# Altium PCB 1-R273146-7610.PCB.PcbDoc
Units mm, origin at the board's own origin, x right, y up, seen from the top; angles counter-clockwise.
Board outline 36.96 x 25.02 mm, 2 copper layers (Top Layer, Bottom Layer), stack 0.536 mm thick; 72 components, 82 nets, 228 pads, 80 vias.
Unrouted connection lines stored in the file: 1.
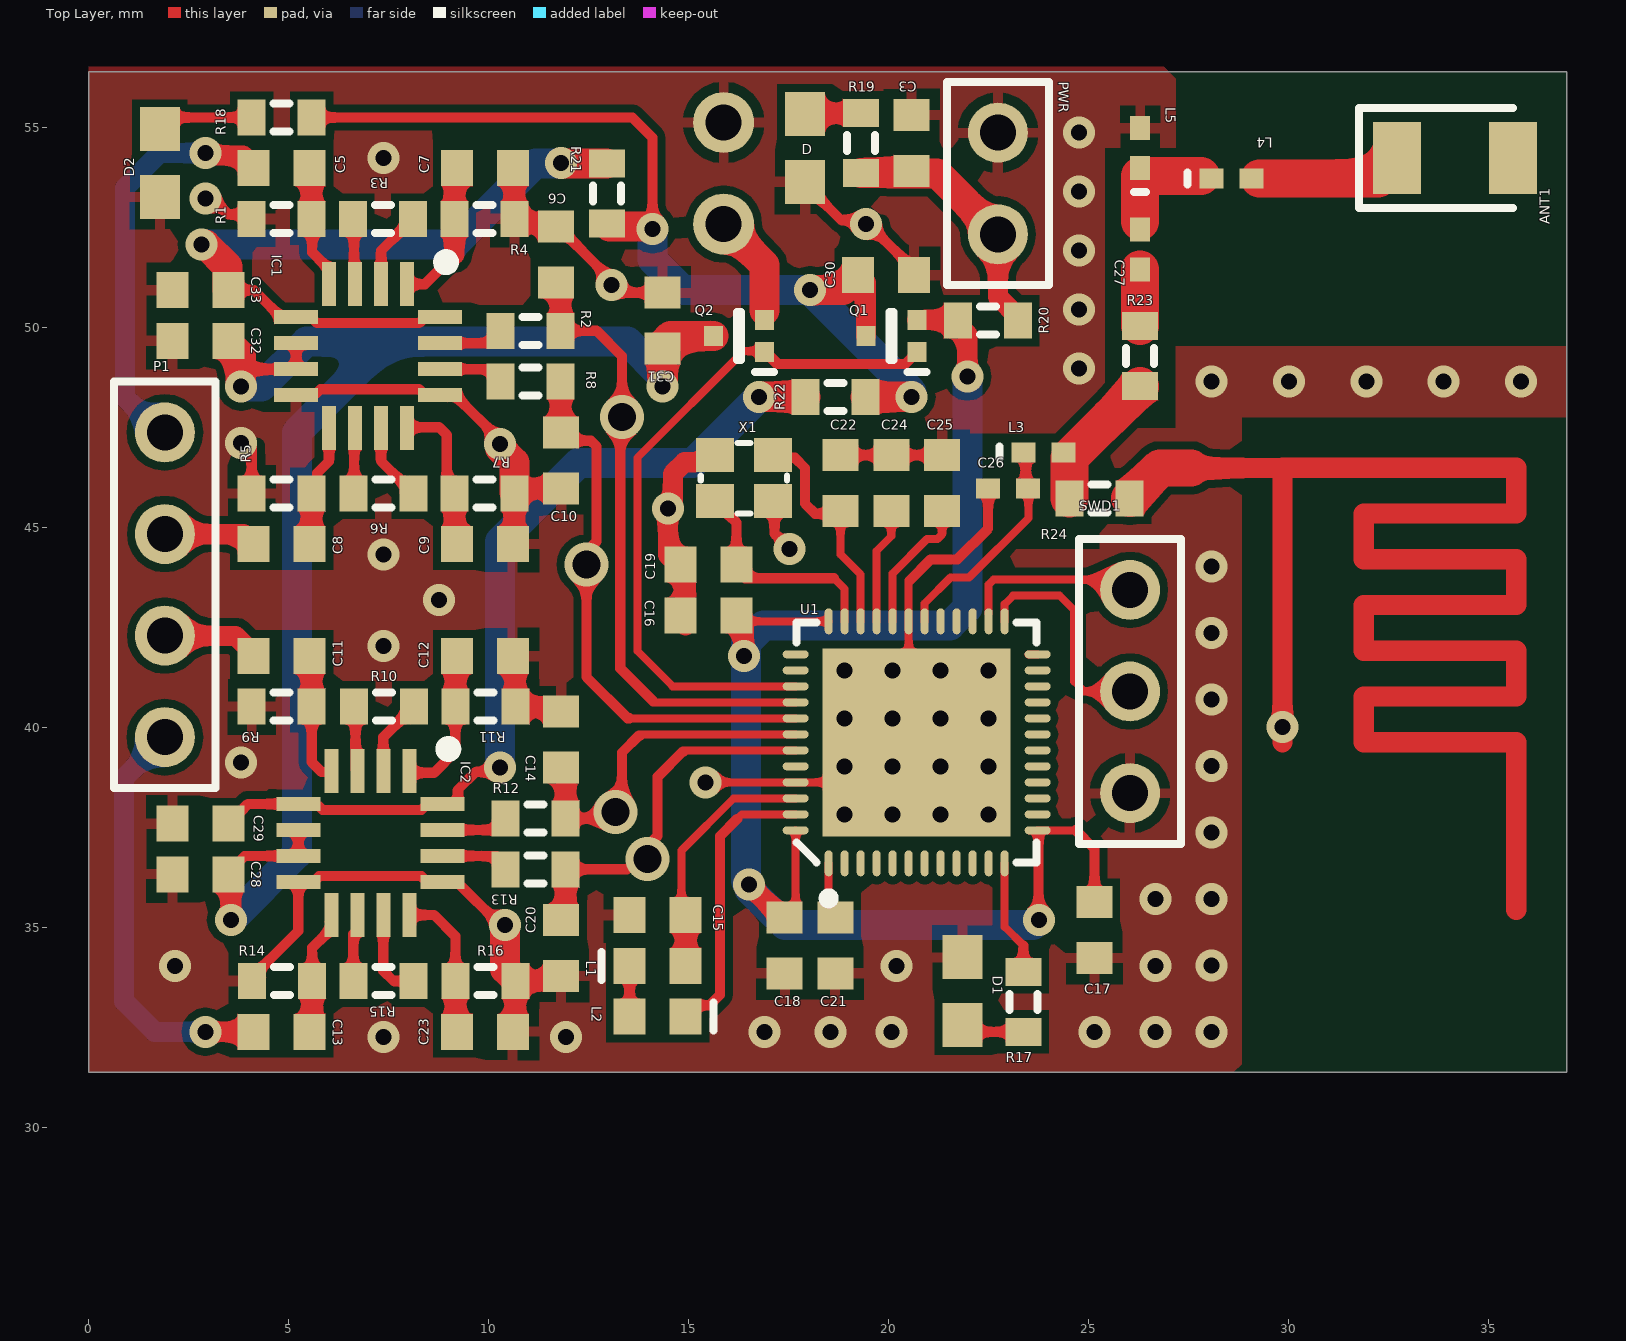
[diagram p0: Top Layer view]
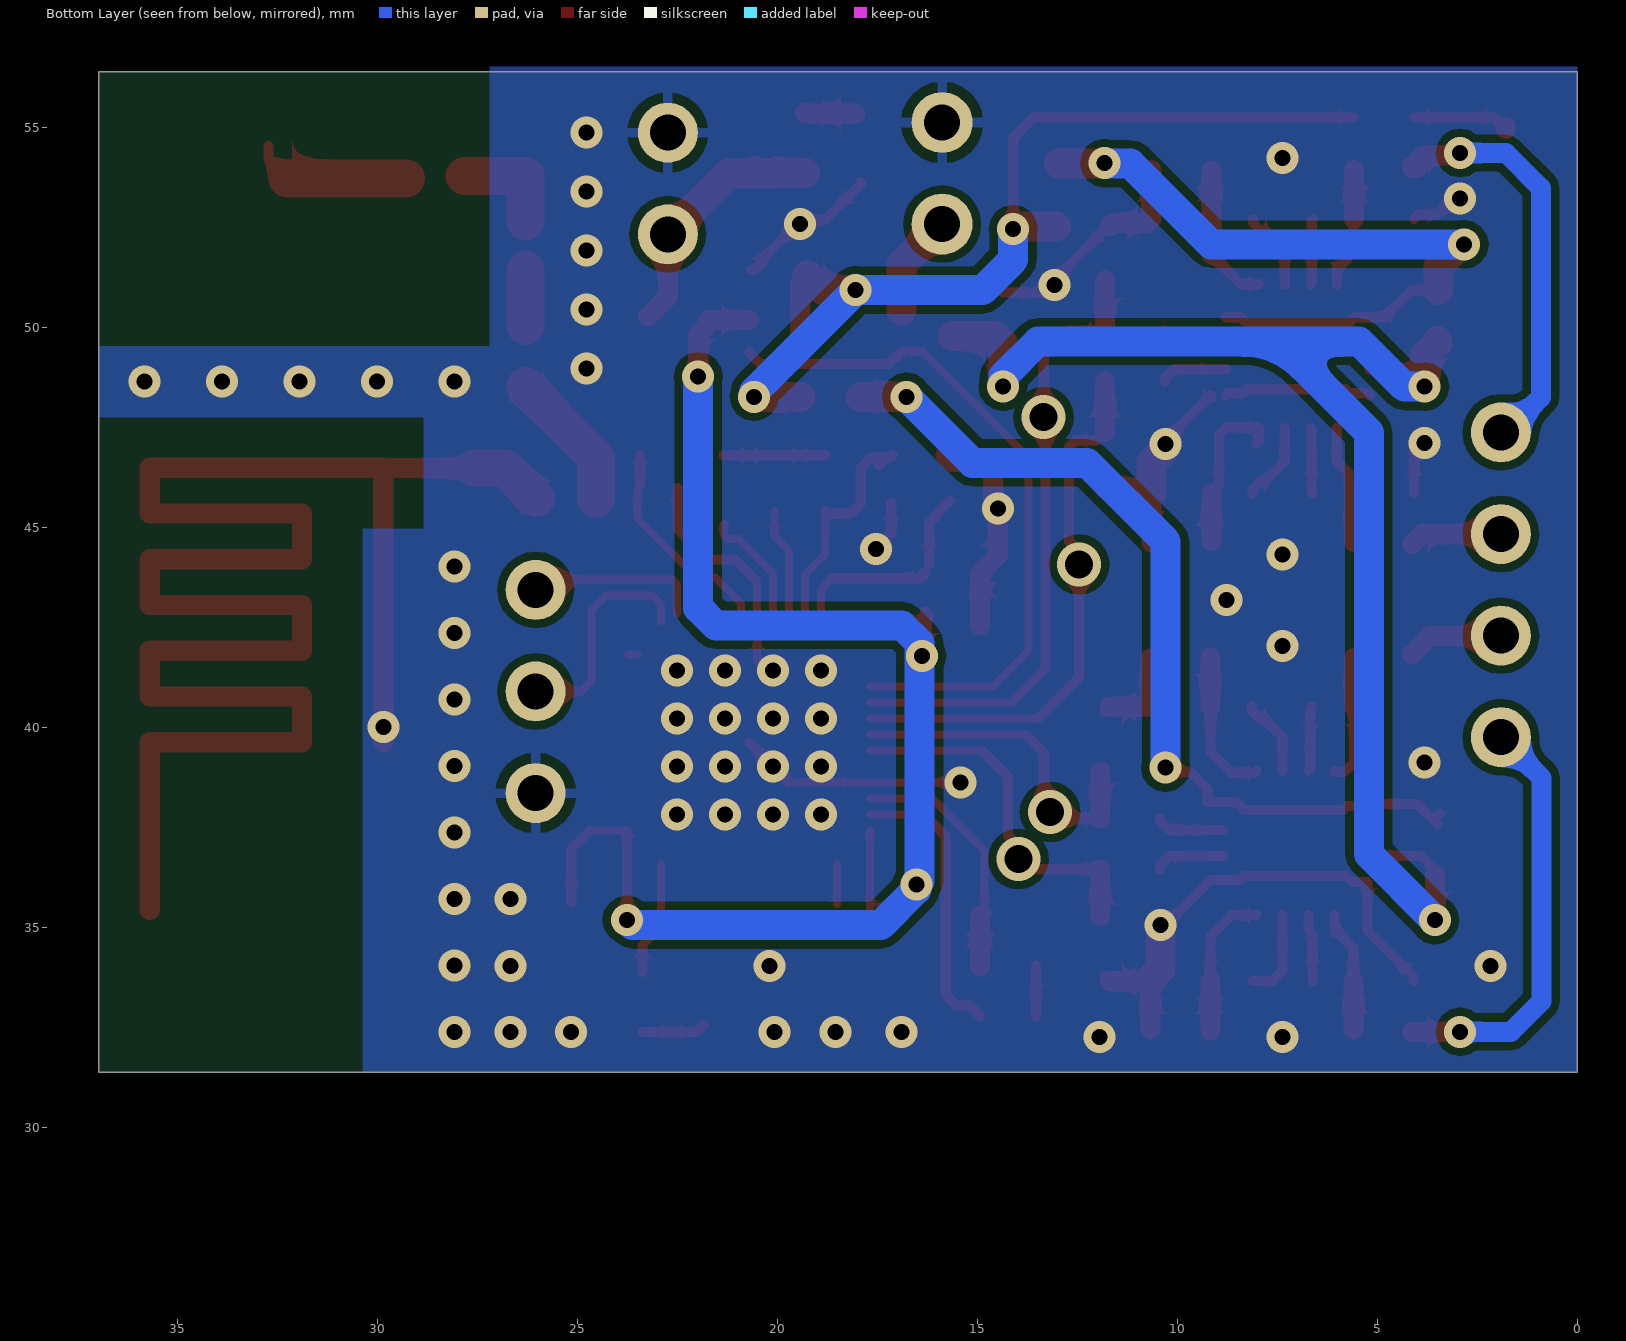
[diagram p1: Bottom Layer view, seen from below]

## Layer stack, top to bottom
Top Solder: solder mask 0.0102, Solder Resist, Dk 3.5
Top Layer: signal copper 0.018
Dielectric 1: dielectric 0.5, FR-4, Dk 4.8
Bottom Layer: signal copper 0.018
Bottom Solder: solder mask 0.0102, Solder Resist, Dk 3.5

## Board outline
0,31.369 36.957,31.369 36.957,56.388 0,56.388

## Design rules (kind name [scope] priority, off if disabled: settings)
Clearance Clearance_2 [InNamedPolygon('VSS_L01_P003')] p1: gap=0.2 ignorepadtopadclearanceinfootprint=FALSE
Clearance Clearance_1 [InNamedPolygon('VSS_L01_P003')] p2: gap=0.254 ignorepadtopadclearanceinfootprint=FALSE except(0: Arc-Hole Track-Hole SMDPad-Hole THPad-Hole Via-Hole Fill-Hole Poly-Hole Region-Hole Text-Hole)
Clearance [All] p3: gap=0.2 ignorepadtopadclearanceinfootprint=TRUE
MatchedLengths MatchLengths_xSignals_U1_L3 [InxSignalClass('xSignals_U1_L3_MatchLengthsClass')] p1: tolerance=2.54 checknetsindiffpair=FALSE checkdiffpairvsdiffpair=TRUE checkxsignals=TRUE checkothers=TRUE
PolygonConnect PolygonConnect_3 [All vs IsNamedPolygon('VSS_L02_P001')] p1: thpad.connectstyle=Relief thpad.reliefconductorwidth=0.254 thpad.reliefentries=4 thpad.polygonreliefangle="90 Angle" thpad.airgapwidth=0.254 smdpad.connectstyle=Relief smdpad.reliefconductorwidth=0.254 smdpad.reliefentries=4 smdpad.polygonreliefangle="90 Angle" smdpad.airgapwidth=0.254 via.connectstyle=Direct via.reliefconductorwidth=0.254 via.reliefentries=4 via.polygonreliefangle="90 Angle" via.airgapwidth=0.254
PolygonConnect PolygonConnect_2 [All vs IsNamedPolygon('VSS_L01_P003')] p2: thpad.connectstyle=Relief thpad.reliefconductorwidth=0.254 thpad.reliefentries=4 thpad.polygonreliefangle="90 Angle" thpad.airgapwidth=0.254 smdpad.connectstyle=Relief smdpad.reliefconductorwidth=0.254 smdpad.reliefentries=4 smdpad.polygonreliefangle="90 Angle" smdpad.airgapwidth=0.254 via.connectstyle=Direct via.reliefconductorwidth=0.254 via.reliefentries=4 via.polygonreliefangle="90 Angle" via.airgapwidth=0.254
PolygonConnect PolygonConnect_1 [All vs IsNamedPolygon('VSS_L01_P003')] p3: connectstyle=Direct reliefconductorwidth=0.254 reliefentries=4 polygonreliefangle="90 Angle" airgapwidth=0.254
PolygonConnect [All] p4: connectstyle=Relief reliefconductorwidth=0.254 reliefentries=4 polygonreliefangle="90 Angle" airgapwidth=0.254
RoutingVias [All] p1: holewidth=0.4 width=0.8 viastyle="Through Hole" minholewidth=0.1 minwidth=0.2 maxholewidth=0 maxwidth=5
SolderMaskExpansion [All] p1: expansion=0.102 istentingtop=FALSE
Width [All] p1: maxlimit=5 minlimit=0.2 preferedwidth=0.254
30 further rules are at their usual default settings.

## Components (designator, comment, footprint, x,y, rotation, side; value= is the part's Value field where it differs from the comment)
ANT1 "2450AT18B100E" ANTC3216X140N 34.163,54.229 r0 top
C3 "Cap" CAPC1608L 20.574,54.61 r270 top value=10uF
C5 "Cap" CAPC1608L 4.826,53.975 r0 top value=68nF
C6 "Cap" CAPC1608L 11.684,51.816 r270 top value=10n
C7 "Cap" CAPC1608L 9.906,53.975 r180 top value=68nF
C8 "Cap" CAPC1608L 4.826,44.577 r0 top value=68nF
C9 "Cap" CAPC1608L 9.906,44.577 r180 top value=68nF
C10 "Cap" CAPC1608L 11.811,46.671 r90 top value=10n
C11 "Cap" CAPC1608L 4.826,41.783 r0 top value=68nF
C12 "Cap" CAPC1608L 9.906,41.783 r180 top value=68nF
C13 "Cap" CAPC1608L 4.826,32.385 r0 top value=68nF
C14 "Cap" CAPC1608L 11.811,39.689 r270 top value=10n
C15 "1.0µF" CAPC1608L 14.224,35.306 r0 top
C16 "100nF" CAPC1608L 15.494,42.799 r180 top
C17 "100nF" CAPC1608L 25.146,34.925 r270 top
C18 "100nF" CAPC1608L 17.399,34.544 r270 top
C19 "12pF" CAPC1608L 15.494,44.069 r0 top
C20 "Cap" CAPC1608L 11.811,34.479 r90 top value=10n
C21 "100nF" CAPC1608L 18.669,34.544 r270 top
C22 "12pF" CAPC1608L 18.796,46.101 r270 top
C23 "Cap" CAPC1608L 9.906,32.385 r180 top value=68nF
C24 "100pF" CAPC1608L 20.066,46.101 r90 top
C25 "100pF" CAPC1608L 21.336,46.101 r270 top
C26 "0.8pF" CAPC1005L 22.987,45.974 r0 top value=1.0pF
C27 "1.2pF" CAPC1005L 26.289,51.943 r270 top value=1.0pF
C28 "Cap" CAPC1608L 2.794,36.322 r0 top value=0.1uF
C29 "Cap" CAPC1608L 2.794,37.592 r0 top value=0.1uF
C30 "Cap" CAPC1608L 19.939,51.308 r180 top value=10uF
C31 "Cap" CAPC1608L 14.351,50.165 r270 top value=10uF
C32 "Cap" CAPC1608L 2.794,49.657 r0 top value=0.1uF
C33 "Cap" CAPC1608L 2.794,50.927 r0 top value=0.1uF
D "TLMB1100-GS08" 0603 17.907,54.483 r90 top
D1 "TLMB1100-GS08" 0603 21.844,33.401 r270 top
D2 "TLMB1100-GS08" 0603 1.778,54.102 r90 top
IC1 "AD8426ACPZ-WP" QFN65P400X400X100-16N-D 6.985,49.276 r270 top
IC2 "AD8426ACPZ-WP" QFN65P400X400X100-16N-D 7.041,37.106 r270 top
L1 "15nH" INDC1608L 14.224,34.036 r0 top value=3.3nH
L2 "10uH" INDC1608L 14.224,32.766 r180 top value=3.3nH
L3 "3.9nH" INDC1005AL 23.868,46.863 r0 top value=3.3nH
L4 "3.3nH" INDC1005AL 28.575,53.721 r0 top
L5 "2.7nH" INDC1005AL 26.289,54.483 r90 top value=3.3nH
P1 "Header 4" HDR1X4 1.905,39.751 r90 top
PWR "Header 2" HDR1X2 22.733,52.324 r90 top
Q1 "RZM002P02T2L" SOTFL40P120X55-3N 20.066,49.784 r180 top
Q2 "RZM002P02T2L" SOTFL40P120X55-3N 16.256,49.784 r180 top
R1 "Res1" RESC1608L 4.826,52.705 r0 top value=2.2M
R2 "Res1" RESC1608L 11.049,49.911 r180 top value=1.56k
R3 "Res1" RESC1608L 7.354,52.705 r0 top value=249
R4 "Res1" RESC1608L 9.894,52.705 r0 top value=2.2M
R5 "Res1" RESC1608L 4.826,45.847 r0 top value=2.2M
R6 "Res1" RESC1608L 7.366,45.847 r0 top value=249
R7 "Res1" RESC1608L 9.894,45.847 r0 top value=2.2M
R8 "Res1" RESC1608L 11.049,48.641 r180 top value=1.56k
R9 "Res1" RESC1608L 4.826,40.513 r0 top value=2.2M
R10 "Res1" RESC1608L 7.378,40.513 r0 top value=249
R11 "Res1" RESC1608L 9.918,40.513 r0 top value=2.2M
R12 "Res1" RESC1608L 11.176,37.719 r180 top value=1.56k
R13 "Res1" RESC1608L 11.176,36.449 r180 top value=1.56k
R14 "Res1" RESC1608L 4.838,33.655 r0 top value=2.2M
R15 "Res1" RESC1608L 7.366,33.655 r0 top value=249
R16 "Res1" RESC1608L 9.918,33.655 r0 top value=2.2M
R17 "Res1" RESC1608L 23.368,33.135 r270 top value=1k
R18 "Res1" RESC1608L 4.826,55.245 r180 top value=1k
R19 "Res1" RESC1608L 19.304,54.61 r90 top value=1k
R20 "Res1" RESC1608L 22.479,50.165 r0 top value=0
R21 "Res1" RESC1608L 12.954,53.34 r270 top value=0
R22 "Res1" RESC1608L 18.669,48.26 r0 top value=0
R23 "Res1" RESC1608L 26.289,49.276 r270 top value=0
R24 "Res1" RESC1608L 25.273,45.72 r180 top value=0
SWD1 "Header 3" HDR1X3 26.035,43.434 r270 top
U1 "nRF52832-QFAA" QFN40P600X600X90-48N 20.701,39.624 r90 top
X1 "32MHz" BT-XTAL_2016 16.383,46.228 r180 top

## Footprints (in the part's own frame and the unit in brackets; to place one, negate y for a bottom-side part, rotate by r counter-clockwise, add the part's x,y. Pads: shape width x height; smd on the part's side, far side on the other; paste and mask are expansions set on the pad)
0603 [mm]
  rect 1.1x1 smd: 1(-0.85,0) 2(0.85,0)
ANTC3216X140N [mm]
  rect 1.2x1.8 smd: 1(-1.45,0) 2(1.45,0)
  silkscreen extent -2.4,-1.25 1.45,1.25, body extent -1.6,-0.8 1.6,0.8, height 1.4
BT-XTAL_2016 [mm]
  rect 0.95x0.85 smd: 1(-0.725,-0.575) 2(0.725,-0.575) 3(0.725,0.575) 4(-0.725,0.575)
  silkscreen extent -1.08,-0.88 1.08,0.88, body extent -1.05,-0.85 1.05,0.85, height 0.56
CAPC1005L [mm] "Chip Capacitor, Body 1.0x0.5mm, IPC High Density"
  rect 0.6x0.5 smd: 1(-0.5,0) 2(0.5,0)
  body extent -0.55,-0.3 0.55,0.3, height 0.6
CAPC1608L [mm] "Chip Capacitor, Body 1.6x0.8mm, IPC High Density"
  rect 0.8x0.9 smd: 1(-0.7,0) 2(0.7,0)
  body extent -0.87,-0.48 0.87,0.48, height 0.85
HDR1X2 [mm] "Connector; Header; 2 Position"
  round 1.5 hole 0.9: 1(0,0) 2(2.54,0)
  silkscreen extent -1.27,-1.27 3.81,1.27
HDR1X3 [mm] "Connector; Header; 3 Position"
  round 1.5 hole 0.9: 1(0,0) 2(2.54,0) 3(5.08,0)
  silkscreen extent -1.27,-1.27 6.35,1.27
HDR1X4 [mm] "Connector; Header; 4 Position"
  round 1.5 hole 0.9: 1(0,0) 2(2.54,0) 3(5.08,0) 4(7.62,0)
  silkscreen extent -1.27,-1.27 8.89,1.27
INDC1005AL [mm] "Chip Inductor, Body 1.0x0.5mm, IPC High Density"
  rect 0.6x0.5 smd: 1(-0.5,0) 2(0.5,0)
  silkscreen extent -1.1,-0.15 -1.1,0.15, body extent -0.55,-0.3 0.55,0.3, height 0.55
INDC1608L [mm] "Chip Inductor, Body 1.6x0.8mm, IPC High Density"
  rect 0.8x0.9 smd: 1(-0.7,0) 2(0.7,0)
  silkscreen extent -1.4,-0.35 -1.4,0.35, body extent -0.87,-0.48 0.87,0.48, height 0.55
QFN40P600X600X90-48N [mm]
  oval 0.65x0.2 smd: 1(-3.025,2.2) 2(-3.025,1.8) 3(-3.025,1.4) 4(-3.025,1) 5(-3.025,0.6) 6(-3.025,0.2) 7(-3.025,-0.2) 8(-3.025,-0.6) 9(-3.025,-1) 10(-3.025,-1.4) 11(-3.025,-1.8) 12(-3.025,-2.2) 25(3.025,-2.2) 26(3.025,-1.8) 27(3.025,-1.4) 28(3.025,-1) 29(3.025,-0.6) 30(3.025,-0.2) 31(3.025,0.2) 32(3.025,0.6) 33(3.025,1) 34(3.025,1.4) 35(3.025,1.8) 36(3.025,2.2)
  oval 0.2x0.65 smd: 13(-2.2,-3.025) 14(-1.8,-3.025) 15(-1.4,-3.025) 16(-1,-3.025) 17(-0.6,-3.025) 18(-0.2,-3.025) 19(0.2,-3.025) 20(0.6,-3.025) 21(1,-3.025) 22(1.4,-3.025) 23(1.8,-3.025) 24(2.2,-3.025) 37(2.2,3.025) 38(1.8,3.025) 39(1.4,3.025) 40(1,3.025) 41(0.6,3.025) 42(0.2,3.025) 43(-0.2,3.025) 44(-0.6,3.025) 45(-1,3.025) 46(-1.4,3.025) 47(-1.8,3.025) 48(-2.2,3.025)
  rect 4.7x4.7 smd: 49(0,0)
  silkscreen extent -4.02,-3 3,3, body extent -3.02,-3.02 3.02,3.02, height 0.86
QFN65P400X400X100-16N-D [mm]
  rect 1.1x0.35 smd: 1(-1.8,0.975) 2(-1.8,0.325) 3(-1.8,-0.325) 4(-1.8,-0.975) 9(1.8,-0.975) 10(1.8,-0.325) 11(1.8,0.325) 12(1.8,0.975)
  rect 0.35x1.1 smd: 5(-0.975,-1.8) 6(-0.325,-1.8) 7(0.325,-1.8) 8(0.975,-1.8) 13(0.975,1.8) 14(0.325,1.8) 15(-0.325,1.8) 16(-0.975,1.8)
  silkscreen extent -2.51,1.79 -2.19,2.11, body extent -2.05,-2.05 2.05,2.05, height 1
RESC1608L [mm] "Chip Resistor, Body 1.6x0.8mm, IPC High Density"
  rect 0.7x0.9 smd: 1(-0.75,0) 2(0.75,0)
  silkscreen extent -0.2,-0.35 0.2,0.35, body extent -0.85,-0.48 0.85,0.48, height 0.6
SOTFL40P120X55-3N [mm]
  rect 0.475x0.5 smd: 1(-0.638,0.4) 2(-0.638,-0.4) 3(0.638,0)
  silkscreen extent -0.87,-0.6 0.05,0.9, body extent -0.6,-0.6 0.6,0.6, height 0.55

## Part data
ANT1: "Antenna", Manufacturer_Name="JOHANSON TECHNOLOGY", Mouser Part Number=609-2450AT18B100E
C3 C5 C6 C7 C8 C9 C10 C11 C12 C13 C14 C20 C23 C28 C29 C30 C31 C32 C33: "Capacitor"
C15: library part C0402-1µ0, "Capacitor, X5R, ±5%"
C16 C17 C18 C21: library part C0201-100n, "Capacitor, X7R, ±10%"
C19 C22: library part C0201-12p, "Capacitor, NP0, ±2%"
C24 C25: library part C0201-100p, "Capacitor, NP0, ±5%"
C26 C27: library part C0201-1.0p, "Capacitor, NP0, ±5%"
D D1 D2: "Blue 466nm LED Indication - Discrete 3.9V 0603 (1608 Metric)", Package="0603 Vishay"
IC1 IC2: "Integrated Circuit", Manufacturer_Name="Analog Devices", Mouser Part Number=584-AD8426ACPZ-WP
L1 L2 L3 L4 L5: library part L0201-3n3, "High frequency chip inductor ±5%"
P1: "Header, 4-Pin"
PWR: "Header, 2-Pin"
Q1 Q2: "MOSFET (P-Channel)", Manufacturer_Name="ROHM Semiconductor", Mouser Part Number=755-RZM002P02T2L
R1 R2 R3 R4 R5 R6 R7 R8 R9 R10 R11 R12 R13 R14 R15 R16 R17 R18 R19 R20 R21 R22 R23 R24: "Resistor"
SWD1: "Header, 3-Pin"
U1: "Multi-protocol Bluetooth Low Energy, ANT and 2.4GHz proprietary system-on-chip", Manufacturer="Nordic Semiconductor"
X1: library part XTAL_SMD2016_32MHz_8pF_Epson, "XTAL SMD 2016, 32MHz, Cl=8pF, Total Tol: ±40ppm", Manufacturer="Epson Toyocom", Manufacturer Part Number=Q22FA12800025, Supplier part number=171-2806

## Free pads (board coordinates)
  round 1.524 hole 0.9: 2(15.875,52.578) 2(15.875,55.118)

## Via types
v1: diameter 0.8, hole 0.4, Top Layer to Bottom Layer, 76 vias
v2: diameter 1.1, hole 0.7, Top Layer to Bottom Layer, 4 vias

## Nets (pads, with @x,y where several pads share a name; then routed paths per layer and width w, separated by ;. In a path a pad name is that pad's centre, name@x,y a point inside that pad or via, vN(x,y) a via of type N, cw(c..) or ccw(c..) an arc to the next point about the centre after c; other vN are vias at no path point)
AIN0: U1.4
AIN1: U1.5
AIN2: U1.6
AIN3: U1.7
AIN4: C6.2 R2.1 U1.40 | length 15.6
  Top Layer w0.2: 14.113,40.624 U1.40
  Top Layer w0.254: C6.2@11.672,51.104 C6.2 ; R2.1 12.7,49.911 13.335,49.276 v2(13.335,47.752) 13.289,47.706 13.289,41.475 14.113,40.651
  Top Layer w0.5: R2.1 C6.2@11.799,51.169
AIN5: C10.2 R8.1 U1.41 | length 13.8
  Top Layer w0.2: 13.525,40.224 U1.41
  Top Layer w0.254: C10.2 12.017,47.165 12.551,47.165 12.7,47.017 12.7,44.652 12.446,44.398 12.446,41.253 13.475,40.224 13.525,40.224
  Top Layer w0.5: C10.2@11.799,47.383 R8.1
  other v2: 12.446,44.069
AIN6: C14.2 R12.1 U1.42 | length 8.7
  Top Layer w0.2: 13.789,39.797 13.816,39.824 U1.42
  Top Layer w0.254: C14.2 C14.2@11.926,38.874 ; R12.1 13.008,37.719 13.335,38.046 13.335,39.37 13.762,39.797 13.789,39.797
  Top Layer w0.5: R12.1 C14.2@11.926,38.874
  other v2: 13.172,37.882
AIN7: C20.2 R13.1 U1.43 | length 9.4
  Top Layer w0.2: 14.886,39.397 14.913,39.424 U1.43
  Top Layer w0.254: C20.2 C20.2@11.926,35.294 ; R13.1 13.462,36.449 v2@13.716,36.703 ; v2(13.97,36.703) 13.766,36.703 13.702,36.767 14.224,37.288 14.224,38.762 14.859,39.397 14.886,39.397
  Top Layer w0.5: C20.2@11.926,35.294 R13.1
ANT: C26.2 L3.1 U1.30 | length 5.4
  Top Layer w0.2: U1.30 20.901,43.099 21.544,43.742 22.01,43.742 23.495,45.227 23.495,45.966 C26.2
  Top Layer w0.254: C26.2@23.427,46.034 L3.1@23.427,46.804
AREF: C28.2 C31.2 C32.2 IC1.6 IC1.7 IC2.6 IC2.7 Q2.3 | length 37.1
  Top Layer w0.254: C28.2 3.494,36.372 3.903,36.781 IC2.7 IC2.6 ; 3.621,48.951 IC1.7 IC1.6
  Top Layer w0.5: v1(3.556,35.179) C28.2@3.556,36.322
  Top Layer w0.75: C32.2 3.494,49.607 3.81,49.291 v1(3.81,48.514) ; v1(14.351,48.514) C31.2 ; C31.2@14.351,49.592 14.543,49.784 Q2.3
  Bottom Layer w0.75: v1(3.556,35.179) 5.207,36.83 5.207,47.371 7.479,49.643 ; v1(3.81,48.514) 4.318,48.514 5.447,49.643 7.479,49.643 ; v1@14.351,48.641 14.341,48.651 14.341,48.778 13.476,49.643 7.479,49.643
AVDD: C30.2 Q1.3 R18.1 R21.2 R22.2 | length 25.1
  Top Layer w0.254: R18.1 13.589,55.245 14.097,54.737 v1(14.097,52.451) v1@14.028,52.52 ; R21.2 R21.2@13.024,52.52 ; C30.2 C30.2@19.428,51.119
  Top Layer w0.5: Q1.3 C30.2@19.428,51.119
  Top Layer w0.75: R21.2@13.024,52.52 v1@14.028,52.52 ; v1(18.034,50.927) 18.858,50.927 C30.2 ; R22.2 v1(20.574,48.26)
  Bottom Layer w0.75: v1(14.097,52.451) 14.097,51.689 14.859,50.927 v1(18.034,50.927) 20.574,48.387 v1(20.574,48.26)
AVDD1: C33.2 IC1.5 IC1.16 R21.1 | length 18.5
  Top Layer w0.254: C33.2 4.134,50.927 4.81,50.251 IC1.5 5.56,50.251 5.708,50.103 8.262,50.103 8.41,50.251 IC1.16 ; v1@11.817,54.096 v1(11.811,54.102) 11.811,53.995 v1@11.958,53.848 ; R21.1@12.948,54.096 R21.1
  Top Layer w0.5: R21.1 R21.1@12.98,54.116
  Top Layer w0.75: v1(2.826,52.07) 2.921,52.07 3.469,51.522 C33.2@3.469,50.927 ; v1@11.817,54.096 R21.1@12.948,54.096
  Bottom Layer w0.75: v1(2.826,52.07) 9.144,52.07 11.166,54.092 11.801,54.092 v1(11.811,54.102)
AVDD2: C29.2 IC2.5 IC2.16 R22.1 | length 22.5
  Top Layer w0.254: C29.2@3.429,37.846 C29.2@3.448,37.827 ; C29.2 3.983,38.081 IC2.5 5.289,38.033 5.752,38.033 5.852,37.933 8.318,37.933 8.514,38.129 9.234,38.129 9.234,38.444 9.675,38.885 10.183,38.885 v1(10.287,38.989)
  Top Layer w0.75: v1(16.764,48.26) R22.1
  Bottom Layer w0.75: v1(10.287,38.989) 10.287,44.646 12.25,46.609 15.113,46.609 v1(16.764,48.26)
BAT: C3.2 PWR.1 R19.1 R20.2 | length 7.1
  Top Layer w0.254: R20.2 R20.2@23.229,50.265
  Top Layer w0.5: PWR.1 22.733,50.761 R20.2@23.229,50.265
  Top Layer w0.75: R19.1 19.306,53.858 20.476,53.858 C3.2 C3.2@20.638,53.846 ; 20.003,53.846 21.211,53.846 PWR.1
DCC: L2.1 U1.47 | length 7.2
  Top Layer w0.2: 16.216,37.71 16.33,37.824 U1.47
  Top Layer w0.254: L2.1 14.924,32.775 15.197,33.048 15.522,33.048 15.783,33.309 15.783,37.277 16.216,37.71
DEC1: C21.1 U1.1 | length 1.4
  Top Layer w0.2: C21.1@18.501,35.586 18.501,36.218 ; 18.501,36.218 U1.1 18.501,36.218
DEC2: C25.2 U1.32 | length 3.2
  Top Layer w0.2: U1.32 20.101,43.847 20.958,44.704 21.219,44.704 21.336,44.821 21.336,45.032 21.286,45.082 C25.2@21.336,45.082
DEC3: C24.1 U1.33 | length 2.9
  Top Layer w0.2: U1.33 19.701,44.412 20.066,44.777 C24.1
DEC4: C15.2 L1.2 U1.46 | length 6.3
  Top Layer w0.2: C15.2@14.732,35.368 14.82,35.456 14.82,36.918 16.126,38.224 U1.46
  Top Layer w0.5: L1.2 C15.2
E1: C5.1 P1.4 | length 10.5
  Top Layer w0.254: v1(2.921,54.356) v1@2.979,54.298 ; C5.1 C5.1@4.126,54.025
  Top Layer w0.5: v1@2.979,54.298 3.853,54.298 C5.1@4.126,54.025 ; C5.1@4.002,53.975 4.064,54.037 C5.1
  Bottom Layer w0.5: P1.4 1.778,47.371 0.905,48.244 0.905,53.483 1.778,54.356 v1(2.921,54.356)
E2: C8.1 P1.3 | length 2.3
  Top Layer w0.5: P1.3 3.872,44.831 C8.1
E3: C11.1 P1.2 | length 2.6
  Top Layer w0.254: C11.1@4.126,41.833 C11.1 C11.1@4.191,41.848
  Top Layer w0.5: P1.2 1.912,42.284 3.676,42.284 C11.1@4.126,41.833
E4: C13.1 P1.1 | length 10.6
  Top Layer w0.5: v1(2.921,32.385) C13.1
  Bottom Layer w0.5: P1.1 0.889,38.735 0.889,33.147 1.651,32.385 v1(2.921,32.385)
IN1+: C5.2 IC1.4 R1.2 | length 3.1
  Top Layer w0.254: C5.2 C5.2@5.576,53.925 ; R1.2 5.588,52.693 5.588,51.873 6.01,51.451 IC1.4
  Top Layer w0.5: R1.2 C5.2@5.576,53.925
IN1-: C7.2 IC1.1 R4.1 | length 3.7
  Top Layer w0.254: IC1.1 8.404,51.076 9.144,51.816 ; C7.2@9.144,53.913 C7.2
  Top Layer w0.5: 9.144,51.816 R4.1 C7.2@9.144,53.913
IN2+: C8.2 IC1.9 R5.2 | length 3.1
  Top Layer w0.254: C8.2 C8.2@5.576,44.627 ; R5.2 5.715,45.986 5.715,46.355 6.01,46.65 IC1.9
  Top Layer w0.5: C8.2@5.576,44.627 R5.2
IN2-: C9.2 IC1.12 R7.1 | length 4.3
  Top Layer w0.254: IC1.12@8.008,47.098 7.96,47.146 IC1.12 7.982,47.498 8.763,47.498 8.951,47.31 8.951,46.04 R7.1 ; C9.2@9.144,44.639 C9.2
  Top Layer w0.5: C9.2@9.144,44.639 R7.1
IN3+: C11.2 IC2.4 R9.2 | length 3.3
  Top Layer w0.254: C11.2@5.461,41.848 C11.2@5.511,41.898 ; R9.2 5.576,39.128 5.827,38.877 6.037,38.877 IC2.4
  Top Layer w0.5: R9.2 C11.2@5.576,41.733
IN3-: C12.2 IC2.1 R11.1 | length 3.8
  Top Layer w0.254: IC2.1 8.06,38.862 8.636,38.862 9.168,39.394 R11.1 ; C12.2@9.168,41.745 C12.2
  Top Layer w0.5: R11.1 C12.2@9.168,41.745
IN4+: C13.2 IC2.9 R14.2 | length 3.2
  Top Layer w0.254: C13.2 C13.2@5.588,32.447 ; R14.2 5.588,34.486 5.985,34.883 6.018,34.883 6.066,34.931 IC2.9
  Top Layer w0.5: C13.2@5.588,32.447 R14.2
IN4-: C23.2 IC2.12 R16.1 | length 3.8
  Top Layer w0.254: IC2.12 8.636,35.306 9.168,34.774 R16.1 ; C23.2@9.168,32.423 C23.2
  Top Layer w0.5: C23.2@9.168,32.423 R16.1
NetANT1_1: ANT1.1 L4.2 | length 4
  Top Layer w0.254: ANT1.1@32.24,53.721 32.713,54.194 ANT1.1 ANT1.1@32.713,54.529
  Top Layer w0.95: L4.2@29.275,53.721 ANT1.1@32.24,53.721
NetC27_1: C27.1 L4.1 L5.1 | length 2.7
  Top Layer w0.95: C27.1@26.289,52.643 26.289,53.783 L4.1@27.81,53.783
NetD1_2: D1.2 R17.2 | length 1.6
  Top Layer w0.254: D1.2 22.01,32.385 R17.2
NetD2_2: D2.2 R18.2 | length 2.5
  Top Layer w0.254: D2.2 2.071,55.245 R18.2
  Top Layer w0.5: D2.2 D2.2@1.778,55.002
NetD_2: D.2 R19.2 | length 1.3
  Top Layer w0.5: D.2@18.034,55.333 18.048,55.347 19.29,55.347 R19.2
NetL1_1: L1.1 L2.2 | length 1.3
  Top Layer w0.254: L2.2 L1.1
OUT1: IC1.15 R2.2 | length 1.7
  Top Layer w0.254: IC1.15 10.076,49.601 10.299,49.824 R2.2
OUT2: IC1.14 R8.2 | length 1.7
  Top Layer w0.254: IC1.14 10.076,48.951 10.299,48.728 R8.2
OUT3: IC2.15 R12.2 | length 1.7
  Top Layer w0.254: IC2.15 10.203,37.431 10.426,37.654 R12.2
OUT4: IC2.14 R13.2 | length 1.8
  Top Layer w0.254: IC2.14 10.194,36.781 10.426,36.549 R13.2
P0.06: U1.8
P0.07: U1.9
P0.08: U1.10
P0.09: U1.11
P0.010: R17.1 U1.12 | length 2.9
  Top Layer w0.2: U1.12 22.901,35.011 23.368,34.544
  Top Layer w0.254: R17.1 23.368,34.544
P0.11: U1.14
P0.12: U1.15
P0.13: U1.16
P0.14: U1.17
P0.15: U1.18
P0.16: U1.19
P0.17: U1.20
P0.18: U1.21
P0.19: U1.22
P0.20: U1.23
P0.22: U1.27
P0.23: U1.28
P0.24: U1.29
P0.25: U1.37
P0.26: U1.38
P0.27/Gate: Q1.1 Q2.1 U1.39 | length 17.5
  Top Layer w0.2: Q2.1 16.875,49.403 16.383,49.403 13.716,46.736 13.716,41.91 14.602,41.024 U1.39
  Top Layer w0.254: Q2.1 16.894,49.372 17.004,49.261 17.041,49.261 17.22,49.082 20.414,49.082 20.704,49.372 Q1.1
REF: pad.2@15.875,52.578 Q2.2 | length 2.6
  Top Layer w0.75: pad.2@15.875,52.578 16.894,51.559 Q2.2@16.894,50.419
RESET: U1.24 | length 0.2
  Top Layer w0.2: U1.24@23.495,41.824 U1.24
RF: C27.2 R23.1 R24.1 | length 52.2
  Top Layer w0.508: 27.559,46.482 29.845,46.482 ; 29.845,39.627 29.845,46.482 ; 35.687,35.433 35.687,39.624 ; 35.687,39.627 31.877,39.627 31.877,40.77 35.687,40.77 35.687,41.913 31.877,41.913 31.877,43.056 35.687,43.056 35.687,44.199 31.877,44.199 31.877,45.342 35.687,45.342 35.687,46.485 29.845,46.485 29.845,46.482
  Top Layer w0.935: R24.1 26.785,46.482 27.559,46.482
  Top Layer w0.95: R23.1 C27.2
RF_B: L3.2 R23.2 R24.2 | length 3.5
  Top Layer w0.95: R24.2 24.523,46.74 26.289,48.506 R23.2
RG1+: IC1.2 R3.2 | length 2
  Top Layer w0.254: IC1.2 7.31,51.911 7.781,52.382 7.881,52.382 8.104,52.605 R3.2
RG1-: IC1.3 R3.1 | length 1.7
  Top Layer w0.254: R3.1 6.632,52.677 6.632,51.104 IC1.3
RG2+: IC1.11 R6.2 | length 2
  Top Layer w0.254: IC1.11 7.31,46.653 7.793,46.17 7.893,46.17 8.116,45.947 R6.2
RG2-: IC1.10 R6.1 | length 1.6
  Top Layer w0.254: R6.1 6.638,45.869 6.638,47.454 IC1.10
RG3+: IC2.2 R10.2 | length 2
  Top Layer w0.254: IC2.2 7.366,39.751 7.805,40.19 7.905,40.19 8.128,40.413 R10.2
RG3-: IC2.3 R10.1 | length 1.6
  Top Layer w0.254: R10.1 6.672,40.469 6.672,38.95 IC2.3
RG4+: IC2.11 R15.2 | length 2.3
  Top Layer w0.254: IC2.11 7.366,33.909 7.62,33.655 R15.2
RG4-: IC2.10 R15.1 | length 1.7
  Top Layer w0.254: R15.1 6.616,34.831 6.716,34.931 IC2.10
SWDCLK: SWD1.2 U1.25 | length 5.7
  Top Layer w0.2: U1.25 22.901,43.075 23.114,43.288 24.276,43.288 24.638,42.926 24.638,41.148 24.892,40.894 SWD1.2
SWDIO: SWD1.1 U1.26 | length 4.4
  Top Layer w0.2: U1.26@22.501,42.847 22.501,43.571 22.618,43.688 25.781,43.688 SWD1.1
VDD: C16.1 C17.1 C18.1 Q1.2 R20.1 U1.13 U1.36 U1.48 | length 40.2
  Top Layer w0.2: C16.1@16.425,42.649 U1.36 ; C18.1@17.676,35.114 U1.48 ; U1.13 24.679,37.424
  Top Layer w0.254: C16.1@16.298,42.903 C16.1 C16.1@16.383,42.61 ; R20.1@21.71,50.184 R20.1 ; U1.13@23.749,37.338 23.749,35.191 v1(23.755,35.185) ; 24.679,37.424 25.146,36.957 C17.1
  Top Layer w0.5: v1(16.383,41.783) C16.1@16.383,42.61 ; v1(16.51,36.068) C18.1@17.464,35.114 ; Q1.2 R20.1@21.71,50.184 ; R20.1 21.729,50.065 21.971,49.823 v1(21.971,48.768)
  Bottom Layer w0.75: v1(16.383,41.783) 16.383,41.769 16.437,41.716 16.437,36.155 16.51,36.082 v1(16.51,36.068) 16.52,36.058 16.52,35.945 17.413,35.052 23.608,35.052 23.742,35.185 v1(23.755,35.185) ; v1@16.406,41.783 16.393,41.797 16.393,41.806 16.437,41.85 16.437,42.106 16.876,42.545 21.532,42.545 21.971,42.984 v1(21.971,48.768)
VSS: C3.1 C6.1 C7.1 C9.1 C10.1 C12.1 C14.1 C15.1 C16.2 C17.2 C18.2 C19.1 C20.1 C21.2 C22.1 C23.1 C24.2 C25.1 C26.1 C28.1 C29.1 C30.1 C31.1 C32.1 C33.1 D1.1 D2.1 D.1 IC1.8 IC1.13 IC2.8 IC2.13 L5.2 pad.2@15.875,55.118 PWR.2 R1.1 R4.2 R5.1 R7.2 R9.1 R11.2 R14.1 R16.2 SWD1.3 U1.31 U1.45 U1.49 X1.2 X1.4 | length 56.9
  Top Layer w0.2: v1(15.418,38.624) U1.45 U1.49@19.701,38.624 ; U1.49@20.501,41.655 U1.31 20.501,43.643 20.528,43.67
  Top Layer w0.254: v1(2.921,53.213) 3.025,53.109 3.206,53.109 3.494,52.821 3.96,52.821 R1.1 ; v1(3.81,47.107) 3.81,47.096 4.076,46.83 R5.1 ; R14.1 4.088,33.755 5.241,34.908 IC2.8 5.616,36.131 5.764,36.279 8.318,36.279 8.418,36.179 9.168,36.179 10.295,35.052 v1(10.414,35.052) ; IC1.8 5.233,48.349 5.696,48.349 5.796,48.449 8.262,48.449 8.362,48.349 8.737,48.349 IC1.13 ; IC1.13@9.16,48.301 10.287,47.174 v1(10.287,47.076) ; C23.1 C23.1@10.668,32.447 ; C12.1 C12.1@10.668,41.721 ; C9.1 C9.1@10.644,44.615 ; C7.1 C7.1@10.644,53.937 ; R7.2 10.656,45.859 R7.2@10.768,45.971 ; C6.1@11.59,52.61 11.64,52.61 v1@13.069,51.181 ; C20.1@11.687,33.655 C20.1 ; C14.1@11.687,40.513 C14.1 ; v1(13.069,51.054) 13.217,51.054 13.406,50.865 C31.1 ; C19.1 C19.1@14.888,43.975 ; X1.4@17.145,45.616 17.145,44.851 17.526,44.47 v1(17.526,44.45) ; D.1 17.907,53.583 18.808,52.682 19.327,52.682 v1(19.431,52.578) ; C22.1 C25.1 ; v1@19.623,52.451 20.366,51.708 20.366,51.631 20.562,51.435 C30.1@20.639,51.435 ; U1.49@19.701,38.624 v1(20.101,39.024) U1.49 ; 20.528,43.67 21.054,44.196 21.717,44.196 22.487,44.966 C26.1
  Top Layer w0.5: C9.1@10.644,44.615 R7.2 ; C7.1@10.644,53.937 R4.2 10.739,52.61 11.59,52.61 C6.1 ; C23.1@10.668,32.447 R16.2 C20.1@11.687,33.655 ; C12.1@10.668,41.721 R11.2 C14.1@11.687,40.513 ; R7.2@10.768,45.971 C10.1 ; v1(14.478,45.466) 14.478,44.308 14.826,43.959 C19.1@14.826,43.909 ; v1@14.605,45.466 14.605,46.335 14.898,46.628 15.61,46.628 X1.2@15.785,46.803 ; C16.2@14.921,42.545 C19.1@14.921,43.815
  Top Layer w0.75: v1@10.287,46.99 10.287,46.976 10.644,46.619 10.644,45.871 R7.2@10.656,45.859 ; v1(10.414,35.052) 10.414,33.959 10.668,33.705 R16.2
  other v1: 7.366,32.258 11.938,32.258 16.891,32.385 18.542,32.385 20.066,32.385 25.146,32.385 26.67,32.385 28.067,32.385 2.159,34.036 20.193,34.036 26.67,34.036 28.067,34.048 26.67,35.71 28.067,35.71 28.067,37.373 18.901,37.824 20.101,37.824 21.301,37.824 22.501,37.824 18.901,39.024 21.301,39.024 22.501,39.024 28.067,39.035 3.81,39.116 29.845,40.005 18.901,40.224 20.101,40.224 21.301,40.224 22.501,40.224 28.067,40.698 18.901,41.424 20.101,41.424 21.301,41.424 22.501,41.424 7.366,42.037 28.067,42.36 8.763,43.18 28.067,44.023 7.366,44.323 28.067,48.641 30.004,48.641 31.941,48.641 33.877,48.641 35.814,48.641 24.765,48.971 24.765,50.444 24.765,51.918 24.765,53.391 7.366,54.229 24.765,54.864
XC1: C22.2 U1.34 X1.1 | length 5.9
  Top Layer w0.2: C22.2 18.796,44.323 19.301,43.818 U1.34
  Top Layer w0.254: X1.1 17.175,46.736 17.653,46.736 17.907,46.482 17.907,46.216 17.91,46.213 17.91,45.59 18.161,45.339 18.734,45.339 C22.2 ; X1.1@17.399,46.609 X1.1@17.456,46.552
XC2: C19.2 U1.35 X1.3 | length 5.4
  Top Layer w0.2: 18.634,43.723 18.901,43.456 U1.35
  Top Layer w0.254: X1.3 15.708,45.653 16.006,45.355 16.006,45.305 16.194,45.117 C19.2 ; C19.2@16.321,43.865 16.321,43.815 16.413,43.723 18.634,43.723
XL1: U1.2
XL2: U1.3
pads on no net: ANT1.2 U1.44

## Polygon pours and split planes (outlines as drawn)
VSS on Bottom Layer "VSS_L02_P001" (solid, pour order 1): 0,31.369 0,56.515 36.957,56.515 36.957,31.369
VSS on Top Layer "VSS_L01_P003" (solid, remove dead copper, pour order 3): 0,31.369 0,56.515 36.957,56.515 36.957,31.369

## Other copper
Top Layer:
  pour cut-out: 27.178,47.473 25.4,47.473 25.4,54.483 27.178,54.483
  pour cut-out: 25.273,44.45 21.971,44.45 21.971,47.346 25.273,47.346
  pour cut-out: 28.829,41.021 28.829,47.752 37.084,47.752 37.084,31.242 28.83,31.242
  pour cut-out: 27.686,45.974
  pour cut-out: 29.972,26.289
  pour cut-out: 17.399,46.863
  pour cut-out: 18.796,47.244
  pour cut-out: 37.211,53.34
  pour cut-out: 29.845,53.721
  pour cut-out: 37.084,49.53 37.084,56.515 27.178,56.515 27.178,49.53
Bottom Layer:
  pour cut-out: 28.829,47.752 28.829,44.958 30.353,44.958 30.353,31.242 37.084,31.242 37.084,47.752
  pour cut-out: 37.084,56.515 37.084,49.53 27.178,49.53 27.178,56.515

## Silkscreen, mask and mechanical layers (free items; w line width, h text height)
Mechanical 1:
  lines w0.254: 0,55.88 0,56.388 37,56.388 ; 0,56.369 0,31.369 36.957,31.369 36.957,56.388 35.56,56.388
